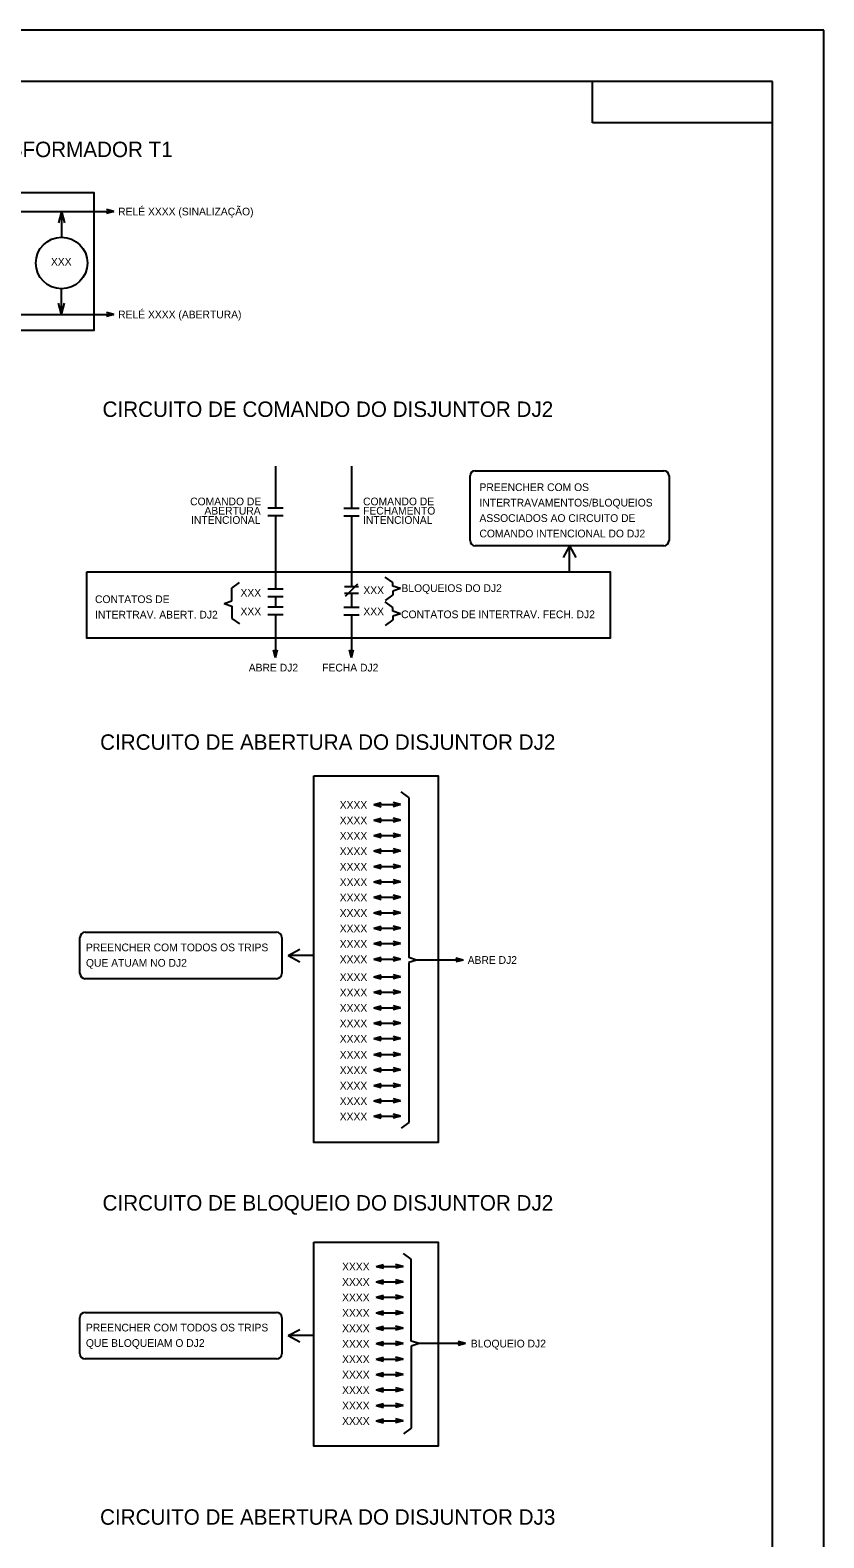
# Model space of a CAD drawing. Extents: x 501 to 1404, y 358 to 952.
# Drawn here: x 1249.3 to 1403.6, y 659.1 to 952 of the extents above; entities that cross this region are included whole.
import ezdxf

# ---------------------------------------------------------------- set-up
doc = ezdxf.new("R2010")
doc.units = 0
doc.layers.add('New Level (0)', color=7, linetype='Continuous')

# ---------------------------------------------------------------- blocks, each defined once
blk = doc.blocks.new('39')
for p, q in [((0, 0), (1.45, 0.39)), ((0, 0), (5.22, 0)), ((0, 0), (1.45, -0.39)), ((5.22, 0), (3.77, 0.39)), ((5.22, 0), (3.77, -0.39))]:
    blk.add_line(p, q)

msp = doc.modelspace()

# ---------------------------------------------------------------- linework, layer by layer
for p, q in [((1265.58, 916.72), (1264.13, 917.11)), ((1206.46, 916.72), (1265.58, 916.72)), ((1255.43, 916.72), (1254.85, 914.55)), ((1255.43, 916.72), (1255.43, 911.72)), ((1255.43, 916.72), (1256.01, 914.55)), ((1265.58, 916.72), (1264.13, 916.33)), ((1255.43, 896.72), (1255.43, 901.72)), ((1243.19, 896.72), (1265.58, 896.72)), ((1255.43, 896.72), (1254.85, 898.89)), ((1255.43, 896.72), (1256.01, 898.89)), ((1265.58, 896.72), (1264.13, 897.11)), ((1265.58, 896.72), (1264.13, 896.33)), ((1296.98, 867.28), (1296.98, 859.1)), ((1311.77, 867.28), (1311.77, 859.1)), ((1298.48, 859.1), (1295.48, 859.1)), ((1310.27, 859.1), (1313.27, 859.1)), ((1298.48, 857.6), (1295.48, 857.6)), ((1296.98, 857.6), (1296.98, 843.36)), ((1310.27, 857.6), (1313.27, 857.6)), ((1311.77, 857.6), (1311.77, 843.86)), ((1288.52, 843.55), (1290.02, 844.63)), ((1288.52, 841.08), (1288.52, 843.55)), ((1310.42, 843.86), (1313.12, 843.86)), ((1310.58, 842), (1312.97, 844.38)), ((1319.78, 844.64), (1318.28, 845.72)), ((1319.78, 843.96), (1319.78, 844.64)), ((1321.28, 843.46), (1319.78, 843.96)), ((1287.02, 840.58), (1288.52, 841.08)), ((1287.02, 840.58), (1288.52, 840.08)), ((1298.48, 843.36), (1295.48, 843.36)), ((1298.48, 841.86), (1295.48, 841.86)), ((1296.98, 841.86), (1296.98, 839.86)), ((1313.12, 842.51), (1310.42, 842.51)), ((1311.77, 842.36), (1311.77, 839.86)), ((1319.78, 842.27), (1318.28, 841.19)), ((1319.78, 839.78), (1318.28, 840.87)), ((1321.28, 843.46), (1319.78, 842.96)), ((1319.78, 842.96), (1319.78, 842.27)), ((1288.52, 840.08), (1288.52, 837.68)), ((1288.52, 837.68), (1290.02, 836.6)), ((1298.48, 839.86), (1295.48, 839.86)), ((1298.48, 838.36), (1295.48, 838.36)), ((1296.98, 838.36), (1296.98, 830.12)), ((1310.27, 839.86), (1313.27, 839.86)), ((1310.27, 839.86), (1313.27, 839.86)), ((1310.27, 838.36), (1313.27, 838.36)), ((1310.27, 838.36), (1313.27, 838.36)), ((1311.77, 838.36), (1311.77, 830.12)), ((1319.78, 839.1), (1319.78, 839.78)), ((1321.28, 838.6), (1319.78, 839.1)), ((1321.28, 838.6), (1319.78, 838.1)), ((1319.78, 838.1), (1319.78, 837.42)), ((1319.78, 837.42), (1318.28, 836.33)), ((1296.98, 830.12), (1296.59, 831.57)), ((1296.98, 830.12), (1297.37, 831.57)), ((1311.77, 830.12), (1311.38, 831.57)), ((1311.77, 830.12), (1312.16, 831.57)), ((1322.92, 802.92), (1321.42, 804)), ((1322.92, 802.92), (1322.92, 771.82)), ((1316.1, 801.5), (1317.55, 801.89)), ((1316.1, 801.5), (1321.32, 801.5)), ((1316.1, 801.5), (1317.55, 801.11)), ((1321.32, 801.5), (1319.87, 801.89)), ((1321.32, 801.5), (1319.87, 801.11)), ((1316.1, 798.5), (1317.55, 798.89)), ((1316.1, 798.5), (1321.32, 798.5)), ((1316.1, 798.5), (1317.55, 798.11)), ((1321.32, 798.5), (1319.87, 798.89)), ((1321.32, 798.5), (1319.87, 798.11)), ((1316.1, 795.5), (1317.55, 795.89)), ((1316.1, 795.5), (1321.32, 795.5)), ((1316.1, 795.5), (1317.55, 795.11)), ((1321.32, 795.5), (1319.87, 795.89)), ((1321.32, 795.5), (1319.87, 795.11)), ((1324.42, 771.32), (1322.92, 771.82)), ((1324.42, 771.32), (1322.92, 770.82)), ((1322.92, 770.82), (1322.92, 739.73)), ((1333.48, 771.32), (1324.42, 771.32)), ((1333.48, 771.32), (1332.03, 771.71)), ((1333.48, 771.32), (1332.03, 770.94)), ((1316.1, 768.06), (1317.55, 768.44)), ((1316.1, 768.06), (1321.32, 768.06)), ((1316.1, 768.06), (1317.55, 767.67)), ((1321.32, 768.06), (1319.87, 768.44)), ((1321.32, 768.06), (1319.87, 767.67)), ((1316.1, 752.96), (1317.55, 753.35)), ((1316.1, 752.96), (1321.32, 752.96)), ((1316.1, 752.96), (1317.55, 752.57)), ((1321.32, 752.96), (1319.87, 753.35)), ((1321.32, 752.96), (1319.87, 752.57)), ((1322.92, 739.73), (1321.42, 738.65)), ((1316.57, 711.81), (1318.02, 712.2)), ((1316.57, 711.81), (1321.79, 711.81)), ((1316.57, 711.81), (1318.02, 711.43)), ((1321.79, 711.81), (1320.34, 712.2)), ((1321.79, 711.81), (1320.34, 711.43)), ((1323.39, 713.23), (1321.89, 714.31)), ((1323.39, 697.31), (1323.39, 713.23)), ((1316.57, 705.81), (1318.02, 706.2)), ((1321.79, 705.81), (1320.34, 706.2)), ((1316.57, 705.81), (1321.79, 705.81)), ((1316.57, 705.81), (1318.02, 705.43)), ((1321.79, 705.81), (1320.34, 705.43)), ((1324.89, 696.81), (1323.39, 697.31)), ((1333.95, 696.81), (1332.5, 697.2)), ((1324.89, 696.81), (1323.39, 696.31)), ((1323.39, 696.31), (1323.39, 680.4)), ((1333.95, 696.81), (1324.89, 696.81)), ((1333.95, 696.81), (1332.5, 696.43)), ((1323.39, 680.4), (1321.89, 679.31))]:
    msp.add_line(p, q)
msp.add_circle((1255.43, 906.72), 5)
at = {"layer": 'New Level (0)'}
for p, q in [((1403.58, 951.96), (562.58, 951.96)), ((1403.58, 951.96), (562.58, 951.96)), ((1403.58, 357.96), (1403.58, 951.96)), ((1403.58, 357.96), (1403.58, 951.96)), ((1393.58, 941.96), (572.58, 941.96)), ((1358.58, 933.96), (1358.58, 941.96)), ((1393.58, 367.96), (1393.58, 941.96)), ((1393.58, 367.96), (1393.58, 941.96)), ((1393.58, 933.96), (1358.58, 933.96)), ((1334.83, 852.79), (1334.83, 865.38)), ((1335.83, 866.38), (1372.48, 866.38)), ((1373.48, 865.38), (1373.48, 852.79)), ((1372.48, 851.79), (1335.83, 851.79)), ((1354.15, 851.79), (1352.94, 849.49)), ((1354.15, 846.76), (1354.15, 851.79)), ((1354.15, 851.79), (1355.36, 849.49)), ((1259.99, 776.72), (1267.34, 776.72)), ((1267.34, 776.72), (1297.21, 776.72)), ((1258.99, 768.69), (1258.99, 775.72)), ((1298.21, 775.72), (1298.21, 768.69)), ((1299.45, 772.2), (1301.75, 773.41)), ((1304.48, 772.2), (1299.45, 772.2)), ((1299.45, 772.2), (1301.75, 770.99)), ((1297.21, 767.69), (1259.99, 767.69)), ((1258.98, 694.84), (1258.98, 701.87)), ((1259.98, 702.87), (1267.33, 702.87)), ((1267.33, 702.87), (1297.21, 702.87)), ((1298.21, 701.87), (1298.21, 694.84)), ((1299.45, 698.36), (1301.74, 699.57)), ((1304.48, 698.36), (1299.45, 698.36)), ((1299.45, 698.36), (1301.74, 697.15)), ((1297.21, 693.84), (1259.98, 693.84))]:
    msp.add_line(p, q, dxfattribs=at)
for points in [[(1197.77, 920.41), (1261.69, 920.41), (1261.69, 893.59), (1197.77, 893.59)], [(1260.35, 846.76), (1362.05, 846.76), (1362.05, 833.87), (1260.35, 833.87)], [(1304.48, 807.12), (1328.61, 807.12), (1328.61, 735.87), (1304.48, 735.87)], [(1304.48, 716.5), (1328.61, 716.5), (1328.61, 676.86), (1304.48, 676.86)]]:
    msp.add_lwpolyline(points, close=True, dxfattribs=at)
for centre, start, end in [((1335.83, 865.38), 90, 180), ((1372.48, 865.38), 0, 90), ((1335.83, 852.79), 180, 270), ((1372.48, 852.79), 270, 0), ((1259.99, 775.72), 90, 180), ((1297.21, 775.72), 0, 90), ((1259.99, 768.69), 180, 270), ((1297.21, 768.69), 270, 0), ((1259.98, 701.87), 90, 180), ((1297.21, 701.87), 0, 90), ((1259.98, 694.84), 180, 270), ((1297.21, 694.84), 270, 0)]:
    msp.add_arc(centre, 1, start, end, dxfattribs=at)

# ---------------------------------------------------------------- block references
for p in [(1316.1, 792.5), (1316.1, 789.5), (1316.1, 786.5), (1316.1, 783.5), (1316.1, 780.5), (1316.1, 777.5), (1316.1, 774.5), (1316.1, 771.5), (1316.1, 765.06), (1316.1, 762.06), (1316.1, 759.06), (1316.1, 756.06), (1316.1, 749.96), (1316.1, 746.96), (1316.1, 743.96), (1316.1, 740.96), (1316.57, 708.81), (1316.57, 702.81), (1316.57, 699.81), (1316.57, 696.81), (1316.57, 693.81), (1316.57, 690.81), (1316.57, 687.81), (1316.57, 684.81), (1316.57, 681.81)]:
    msp.add_blockref('39', p)

# ---------------------------------------------------------------- texts
for s, height, p in [('SINALIZAÇÃO TRANSFORMADOR T1', 3, (1206.59, 927.29)), ('RELÉ XXXX (SINALIZAÇÃO)', 1.5, (1266.42, 915.97)), ('XXX', 1.5, (1253.35, 906.22)), ('RELÉ XXXX (ABERTURA)', 1.5, (1266.42, 895.97)), ('CIRCUITO DE COMANDO DO DISJUNTOR DJ2', 3, (1263.38, 876.82)), ('COMANDO DE', 1.5, (1280.41, 859.65)), ('COMANDO DE ', 1.5, (1314.02, 859.65)), ('PREENCHER COM OS ', 1.5, (1336.64, 862.42)), (' ABERTURA', 1.5, (1282.63, 857.85)), ('FECHAMENTO ', 1.5, (1314.02, 857.85)), ('INTERTRAVAMENTOS/BLOQUEIOS', 1.5, (1336.64, 859.42)), (' INTENCIONAL', 1.5, (1280.03, 856.05)), ('INTENCIONAL', 1.5, (1314.02, 856.05)), ('ASSOCIADOS AO CIRCUITO DE ', 1.5, (1336.64, 856.42)), ('COMANDO INTENCIONAL DO DJ2', 1.5, (1336.64, 853.42)), ('XXX', 1.5, (1314.08, 842.41)), ('BLOQUEIOS DO DJ2', 1.5, (1321.48, 842.81)), ('CONTATOS DE ', 1.5, (1261.92, 840.66)), ('XXX', 1.5, (1290.19, 841.92)), ('INTERTRAV. ABERT. DJ2', 1.5, (1261.92, 837.66)), ('XXX', 1.5, (1290.19, 838.29)), ('XXX', 1.5, (1314.08, 838.29)), ('CONTATOS DE INTERTRAV. FECH. DJ2', 1.5, (1321.41, 837.72)), ('ABRE DJ2', 1.5, (1291.8, 827.37)), ('FECHA DJ2', 1.5, (1306.07, 827.37)), ('CIRCUITO DE ABERTURA DO DISJUNTOR DJ2', 3, (1262.91, 812.16)), ('XXXX', 1.5, (1309.48, 800.7)), ('XXXX', 1.5, (1309.48, 797.7)), ('XXXX', 1.5, (1309.48, 794.7)), ('XXXX', 1.5, (1309.48, 791.7)), ('XXXX', 1.5, (1309.48, 788.7)), ('XXXX', 1.5, (1309.48, 785.7)), ('XXXX', 1.5, (1309.48, 782.7)), ('XXXX', 1.5, (1309.48, 779.7)), ('XXXX', 1.5, (1309.48, 776.7)), ('PREENCHER COM TODOS OS TRIPS', 1.5, (1260.16, 773.02)), ('XXXX', 1.5, (1309.48, 773.7)), ('QUE ATUAM NO DJ2', 1.5, (1260.16, 770.02)), ('XXXX', 1.5, (1309.48, 770.7)), ('ABRE DJ2', 1.5, (1334.35, 770.57)), ('XXXX', 1.5, (1309.48, 767.26)), ('XXXX', 1.5, (1309.48, 764.26)), ('XXXX', 1.5, (1309.48, 761.26)), ('XXXX', 1.5, (1309.48, 758.26)), ('XXXX', 1.5, (1309.48, 755.26)), ('XXXX', 1.5, (1309.48, 752.16)), ('XXXX', 1.5, (1309.48, 749.16)), ('XXXX', 1.5, (1309.48, 746.16)), ('XXXX', 1.5, (1309.48, 743.16)), ('XXXX', 1.5, (1309.48, 740.16)), ('CIRCUITO DE BLOQUEIO DO DISJUNTOR DJ2', 3, (1263.38, 722.65)), ('XXXX', 1.5, (1309.94, 711.02)), ('XXXX', 1.5, (1309.94, 708.02)), ('XXXX', 1.5, (1309.94, 705.02)), ('XXXX', 1.5, (1309.94, 702.02)), ('PREENCHER COM TODOS OS TRIPS', 1.5, (1260.15, 699.17)), ('XXXX', 1.5, (1309.94, 699.02)), ('QUE BLOQUEIAM O DJ2', 1.5, (1260.15, 696.17)), ('XXXX', 1.5, (1309.94, 696.02)), ('BLOQUEIO DJ2', 1.5, (1334.96, 696.06)), ('XXXX', 1.5, (1309.94, 693.02)), ('XXXX', 1.5, (1309.94, 690.02)), ('XXXX', 1.5, (1309.94, 687.02)), ('XXXX', 1.5, (1309.94, 684.02)), ('XXXX', 1.5, (1309.94, 681.02)), ('CIRCUITO DE ABERTURA DO DISJUNTOR DJ3', 3, (1262.9, 661.62))]:
    msp.add_text(s, height=height).set_placement(p)

doc.saveas('drawing.dxf')
